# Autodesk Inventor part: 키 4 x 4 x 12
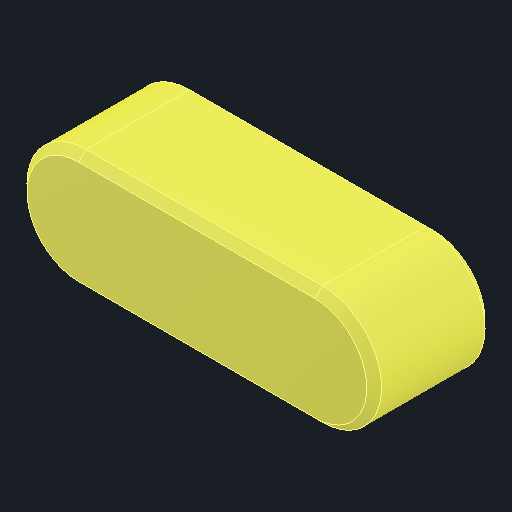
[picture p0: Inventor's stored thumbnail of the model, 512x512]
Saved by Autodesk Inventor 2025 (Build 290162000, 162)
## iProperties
Created: 2025-08
Part Number: 키 4 x 4 x 12
Material: 강철, 연강
Description: 키 및 해당 키홈
Document SubType Name: Modeling
Designer: infra023
Density: 7.85 g/cm^3
Appearance: 기본값
Author: jhkim
Sending System: Autodesk Inventor 2026
Preprocessor: ST-DEVELOPER v20.1
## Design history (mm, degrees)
feature "Solid1"
node "솔리드1"
